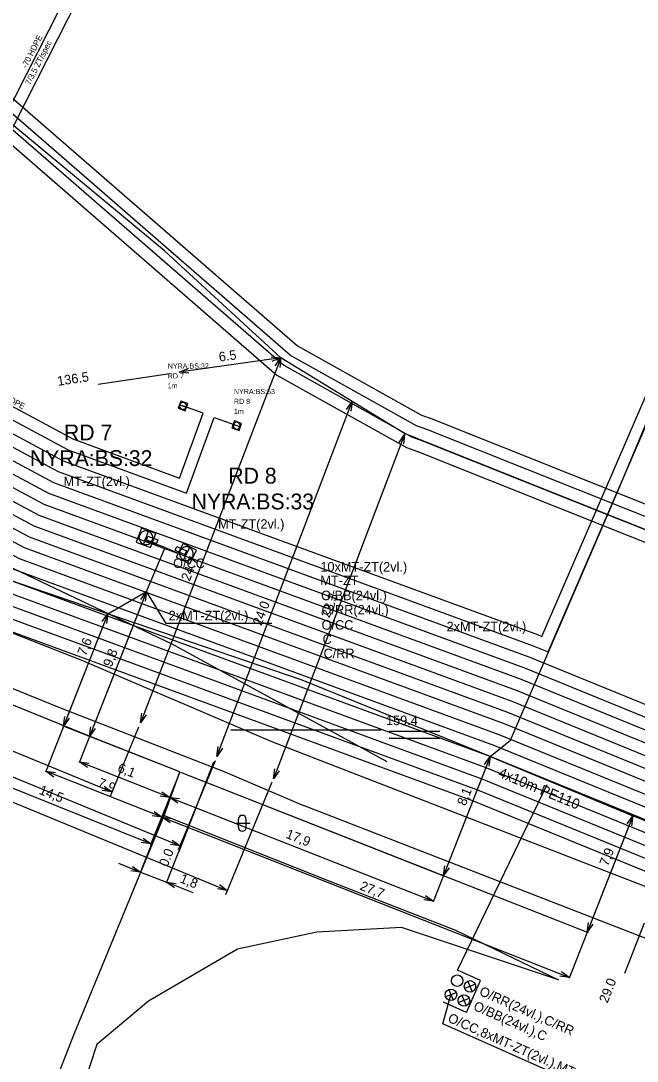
# Model space of a CAD drawing. Extents: x -836739 to -834468, y -1071001 to -1070126.
# Drawn here: x -836379.8 to -836340.8, y -1070425.8 to -1070360.1 of the extents above; entities that cross this region are included whole.
import ezdxf

# ---------------------------------------------------------------- set-up
doc = ezdxf.new("R2010")
doc.units = 0
for name, color, linetype in [('f001_pol_linie', 7, 'Continuous'), ('f001_pol_znacky', 7, 'Continuous'), ('f002_inz_linie_mimo_CETIN', 7, 'Continuous'), ('f003_opt_sit_texty', 7, 'Continuous'), ('f003_opt_sit_znacky', 7, 'Continuous'), ('f003_vynaseci_cary', 7, 'Continuous'), ('f006_osa_trasy', 7, 'Continuous'), ('f006_stp_koty', 7, 'Continuous'), ('f006_stp_linie', 7, 'Continuous'), ('f006_stp_texty', 7, 'Continuous'), ('f007_rezkynet_linie', 7, 'Continuous'), ('f007_rezkynet_texty', 7, 'Continuous'), ('f007_rezkynet_znacky', 7, 'Continuous'), ('f309_rozvadec_opt', 7, 'Continuous'), ('f309_rozvadec_opt_ann', 7, 'Continuous'), ('f309_trubicka', 7, 'Continuous'), ('f309_trubicka_ann', 7, 'Continuous'), ('f309_trubka', 7, 'Continuous')]:
    doc.layers.add(name, color=color, linetype=linetype)

msp = doc.modelspace()

# ---------------------------------------------------------------- linework, layer by layer
at = {"layer": 'f001_pol_linie'}
for points in [[(-836356.62, -1070406.87), (-836370.19, -1070399.44), (-836385.43, -1070392.2), (-836396.38, -1070386.03), (-836404.41, -1070381.11), (-836409.87, -1070376.61), (-836425.28, -1070363.93), (-836449.03, -1070345.44), (-836455, -1070340), (-836462.64, -1070329.11), (-836464.81, -1070325.47), (-836465.74, -1070321.03), (-836464.89, -1070314.87), (-836461.62, -1070306.74), (-836456.41, -1070297.54), (-836450.95, -1070288.2), (-836447.03, -1070272.79), (-836441.38, -1070260.76)], [(-836363.94, -1070405.58), (-836375.83, -1070400.5), (-836396.2, -1070392.51), (-836412.22, -1070385.35), (-836415.3, -1070382.95)], [(-836417.67, -1070386.5), (-836404.61, -1070392.58), (-836394.98, -1070396.26), (-836377.21, -1070403.49), (-836366.86, -1070407.51), (-836361.89, -1070409.63)], [(-836369.71, -1070407.51), (-836374.95, -1070405.45), (-836388.98, -1070399.76), (-836393.4, -1070397.9)], [(-836015.21, -1070459.49), (-836021.84, -1070470.53), (-836029.29, -1070480.55), (-836039.31, -1070497.89), (-836043.1, -1070509.87), (-836044.22, -1070522.08), (-836111.13, -1070487.77), (-836123.74, -1070483.53), (-836128.61, -1070481.99), (-836211.76, -1070460.38), (-836245.95, -1070449.75), (-836279.43, -1070438.33), (-836363.94, -1070405.58)], [(-836407.72, -1070434.26), (-836402.65, -1070436.98), (-836392.21, -1070442.72), (-836384.11, -1070447.06), (-836383.25, -1070443.91), (-836379.69, -1070432.5), (-836376.35, -1070424), (-836370.7, -1070410.27), (-836369.71, -1070407.51)], [(-836046.6, -1070544.35), (-836045.64, -1070538.23), (-836044.38, -1070528.39), (-836045.14, -1070525.37), (-836047.92, -1070523.71), (-836112.97, -1070490.6), (-836124.66, -1070486.54), (-836132.47, -1070484.33), (-836212.77, -1070463.28), (-836247.95, -1070452.55), (-836280.73, -1070441.12), (-836361.89, -1070409.63)], [(-836370.7, -1070410.27), (-836360.12, -1070414.44), (-836352.3, -1070417.49), (-836345.8, -1070420.64)], [(-836345.8, -1070420.64), (-836355.7, -1070417.34), (-836361.05, -1070417.62), (-836366.07, -1070418.7), (-836371.68, -1070421.97), (-836374.95, -1070424.71), (-836382.62, -1070447.97)]]:
    msp.add_lwpolyline(points, dxfattribs=at)
at = {"layer": 'f001_pol_znacky'}
for p, q in [((-836366.01, -1070411), (-836366.01, -1070410.5)), ((-836365.51, -1070411), (-836365.51, -1070410.5)), ((-836366.26, -1070410.75), (-836365.26, -1070410.75))]:
    msp.add_line(p, q, dxfattribs=at)
for centre, start, end in [((-836365.76, -1070410.5), 0, 179.99999), ((-836365.76, -1070411), 179.99999, 359.99999)]:
    msp.add_arc(centre, 0.25, start, end, dxfattribs=at)
at = {"layer": 'f002_inz_linie_mimo_CETIN'}
for points in [[(-836371.81, -1070392.85), (-836371.72, -1070392.62), (-836371.09, -1070392.85), (-836371.18, -1070393.08)], [(-836371.81, -1070392.85), (-836371.72, -1070392.62), (-836371.09, -1070392.85), (-836371.18, -1070393.08)], [(-836371.81, -1070392.85), (-836371.18, -1070393.08)], [(-836371.81, -1070392.85), (-836371.18, -1070393.08)], [(-836370, -1070393.52), (-836369.9, -1070393.29), (-836369.29, -1070393.55), (-836369.39, -1070393.78)], [(-836370, -1070393.52), (-836369.9, -1070393.29), (-836369.29, -1070393.55), (-836369.39, -1070393.78)], [(-836370, -1070393.52), (-836369.39, -1070393.78)], [(-836370, -1070393.52), (-836369.39, -1070393.78)]]:
    msp.add_lwpolyline(points, dxfattribs=at)
at = {"layer": 'f003_opt_sit_znacky'}
for p, q in [((-836371.698, -1070392.326), (-836372.002, -1070393.134)), ((-836371.699, -1070392.326), (-836371.698, -1070392.326)), ((-836369.097, -1070393.344), (-836369.483, -1070394.116)), ((-836369.097, -1070393.344), (-836369.097, -1070393.344))]:
    msp.add_line(p, q, dxfattribs=at)
for points in [[(-836372.466, -1070393.012), (-836371.567, -1070393.349), (-836371.23, -1070392.45), (-836372.129, -1070392.113)], [(-836369.932, -1070393.946), (-836369.073, -1070394.375), (-836368.644, -1070393.516), (-836369.502, -1070393.087)]]:
    msp.add_lwpolyline(points, close=True, dxfattribs=at)
for centre, start, end in [((-836371.847, -1070392.731), 69.80775, 249.08016), ((-836371.847, -1070392.731), 249.03941, 69.84764), ((-836369.288, -1070393.731), 63.79875, 243.07115), ((-836369.287, -1070393.732), 243.0304, 63.83864)]:
    msp.add_arc(centre, 0.432, start, end, dxfattribs=at)
at = {"layer": 'f003_vynaseci_cary'}
msp.add_lwpolyline([(-836363.89, -1070398.15), (-836370.57, -1070398.15), (-836371.81, -1070396.12)], dxfattribs=at)
at = {"layer": 'f006_osa_trasy'}
for points in [[(-836259.51, -1070422.49), (-836273.33, -1070418.13), (-836279.63, -1070415.33), (-836305.65, -1070405.26), (-836332.15, -1070395.46), (-836355.51, -1070386.15), (-836363.32, -1070381.37), (-836370.68, -1070374.62), (-836386.63, -1070361.4), (-836412.6, -1070344.19), (-836444.52, -1070318.16), (-836450.35, -1070293.64), (-836451.12, -1070284.95), (-836453.47, -1070277.02), (-836456.68, -1070270.62)], [(-836350.1, -1070406.54), (-836348.82, -1070405.5), (-836341.98, -1070389.64), (-836337.19, -1070378.21), (-836332.66, -1070368.05), (-836330.1, -1070369.07), (-836327.64, -1070363.27)], [(-836374.26, -1070397.52), (-836380.46, -1070395.41), (-836397.84, -1070386.09), (-836399.2, -1070385.59)], [(-836370.64, -1070393.35), (-836371.91, -1070392.88), (-836371.85, -1070392.73)], [(-836374.26, -1070397.52), (-836371.81, -1070396.12), (-836370.64, -1070393.35)], [(-836370.64, -1070393.35), (-836369.37, -1070393.89), (-836369.29, -1070393.73)], [(-836350.1, -1070406.54), (-836361.97, -1070401.72), (-836374.26, -1070397.52)], [(-836322.53, -1070417.81), (-836341.09, -1070410.29), (-836350.1, -1070406.54)]]:
    msp.add_lwpolyline(points, dxfattribs=at)
at = {"layer": 'f006_stp_koty'}
for p, q in [((-836371.832, -1070396.176), (-836376.061, -1070406.932)), ((-836371.81, -1070396.12), (-836375.407, -1070405.27)), ((-836374.26, -1070397.52), (-836377.053, -1070404.623)), ((-836374.282, -1070397.576), (-836378.194, -1070407.528)), ((-836369.766, -1070407.488), (-836377.108, -1070404.601)), ((-836369.766, -1070407.488), (-836375.463, -1070405.248)), ((-836371.531, -1070412.053), (-836384.999, -1070406.656)), ((-836350.122, -1070406.596), (-836353.709, -1070415.72)), ((-836350.1, -1070406.54), (-836353.055, -1070414.057)), ((-836370.342, -1070409.116), (-836376.039, -1070406.877)), ((-836370.83, -1070410.359), (-836378.173, -1070407.472)), ((-836369.732, -1070407.566), (-836372.216, -1070413.884)), ((-836369.732, -1070407.566), (-836371.553, -1070412.109)), ((-836369.732, -1070407.566), (-836370.852, -1070410.415)), ((-836369.732, -1070407.566), (-836370.852, -1070410.415)), ((-836369.732, -1070407.566), (-836370.363, -1070409.172)), ((-836369.732, -1070407.566), (-836370.363, -1070409.172)), ((-836369.654, -1070407.532), (-836352.999, -1070414.079)), ((-836369.654, -1070407.532), (-836343.919, -1070417.649)), ((-836368.086, -1070408.213), (-836370.57, -1070414.531)), ((-836370.342, -1070409.116), (-836353.687, -1070415.664)), ((-836370.83, -1070410.359), (-836345.095, -1070420.476)), ((-836341.112, -1070410.346), (-836345.116, -1070420.532)), ((-836341.09, -1070410.29), (-836343.975, -1070417.627)), ((-836373.59, -1070413.279), (-836372.194, -1070413.828)), ((-836372.194, -1070413.828), (-836370.548, -1070414.475)), ((-836368.861, -1070415.138), (-836370.548, -1070414.475))]:
    msp.add_line(p, q, dxfattribs=at)
for points in [[(-836363.32, -1070381.37), (-836372.191, -1070404.406)], [(-836363.32, -1070381.37), (-836369.749, -1070382.285)], [(-836363.935, -1070381.306), (-836363.32, -1070381.37), (-836363.892, -1070381.603)], [(-836363.675, -1070381.876), (-836363.32, -1070381.37), (-836363.395, -1070381.983)], [(-836370.331, -1070382.379), (-836374.864, -1070383.063)], [(-836369.133, -1070382.348), (-836369.749, -1070382.285), (-836369.176, -1070382.051)], [(-836435.495, -1070383.458), (-836373.991, -1070408.776)], [(-836367.368, -1070406.528), (-836358.831, -1070384.117)], [(-836359.184, -1070384.624), (-836358.831, -1070384.117), (-836358.904, -1070384.731)], [(-836436.07, -1070384.855), (-836369.694, -1070412.179)], [(-836436.625, -1070386.205), (-836366.711, -1070414.986)], [(-836355.51, -1070386.2), (-836363.79, -1070407.938)], [(-836355.863, -1070386.707), (-836355.51, -1070386.2), (-836355.583, -1070386.814)], [(-836372.169, -1070396.624), (-836371.81, -1070396.12), (-836371.89, -1070396.733)], [(-836374.619, -1070398.024), (-836374.26, -1070397.52), (-836374.34, -1070398.133)], [(-836376.693, -1070404.12), (-836377.053, -1070404.623), (-836376.973, -1070404.01)], [(-836371.835, -1070403.899), (-836372.191, -1070404.406), (-836372.115, -1070403.792)], [(-836375.048, -1070404.767), (-836375.407, -1070405.27), (-836375.327, -1070404.657)], [(-836372.306, -1070404.683), (-836374.105, -1070409.054)], [(-836366.48, -1070404.853), (-836356.983, -1070404.853)], [(-836356.49, -1070404.94), (-836353.28, -1070404.94)], [(-836356.49, -1070405.38), (-836353.28, -1070405.38)], [(-836367.014, -1070406.02), (-836367.368, -1070406.528), (-836367.294, -1070405.913)], [(-836350.459, -1070407.044), (-836350.1, -1070406.54), (-836350.18, -1070407.153)], [(-836375.535, -1070407.236), (-836376.039, -1070406.877), (-836375.425, -1070406.957)], [(-836367.482, -1070406.805), (-836369.808, -1070412.456)], [(-836367.572, -1070406.894), (-836369.775, -1070412.548)], [(-836363.436, -1070407.43), (-836363.79, -1070407.938), (-836363.716, -1070407.323)], [(-836377.669, -1070407.831), (-836378.173, -1070407.472), (-836377.559, -1070407.552)], [(-836374.488, -1070408.408), (-836373.991, -1070408.776), (-836374.602, -1070408.686)], [(-836363.904, -1070408.166), (-836366.825, -1070415.263)], [(-836370.845, -1070408.757), (-836370.342, -1070409.116), (-836370.955, -1070409.036)], [(-836369.838, -1070409.476), (-836370.342, -1070409.116), (-836369.728, -1070409.196)], [(-836371.333, -1070410), (-836370.83, -1070410.359), (-836371.443, -1070410.279)], [(-836370.326, -1070410.718), (-836370.83, -1070410.359), (-836370.217, -1070410.439)], [(-836341.449, -1070410.794), (-836341.09, -1070410.29), (-836341.17, -1070410.903)], [(-836372.032, -1070411.691), (-836371.531, -1070412.053), (-836372.143, -1070411.969)], [(-836370.191, -1070411.811), (-836369.694, -1070412.179), (-836370.305, -1070412.089)], [(-836372.697, -1070413.469), (-836372.194, -1070413.828), (-836372.807, -1070413.748)], [(-836352.696, -1070413.554), (-836353.055, -1070414.057), (-836352.975, -1070413.444)], [(-836370.045, -1070414.834), (-836370.548, -1070414.475), (-836369.935, -1070414.555)], [(-836367.208, -1070414.618), (-836366.711, -1070414.986), (-836367.322, -1070414.896)], [(-836354.19, -1070415.305), (-836353.687, -1070415.664), (-836354.3, -1070415.584)], [(-836343.615, -1070417.124), (-836343.975, -1070417.627), (-836343.895, -1070417.014)], [(-836340.379, -1070417.053), (-836341.625, -1070420.232)], [(-836345.598, -1070420.117), (-836345.095, -1070420.476), (-836345.708, -1070420.396)]]:
    msp.add_lwpolyline(points, dxfattribs=at)
at = {"layer": 'f006_stp_linie'}
msp.add_lwpolyline([(-836350.1, -1070406.54), (-836341.09, -1070410.29)], dxfattribs=at)
at = {"layer": 'f007_rezkynet_linie'}
for points in [[(-836352.169, -1070420.019), (-836346.503, -1070408.308)], [(-836341.211, -1070428.682), (-836353.103, -1070423.416), (-836352.583, -1070421.575)]]:
    msp.add_lwpolyline(points, dxfattribs=at)
at = {"layer": 'f007_rezkynet_znacky'}
for p, q in [((-836350.706, -1070420.667), (-836352.169, -1070420.019)), ((-836351.038, -1070420.917), (-836351.716, -1070421.178)), ((-836351.599, -1070422.685), (-836350.706, -1070420.667)), ((-836351.508, -1070420.709), (-836351.246, -1070421.386)), ((-836352.244, -1070421.444), (-836352.922, -1070421.705)), ((-836352.714, -1070421.236), (-836352.452, -1070421.913)), ((-836351.422, -1070421.808), (-836352.099, -1070422.069)), ((-836351.892, -1070421.6), (-836351.629, -1070422.277)), ((-836353.077, -1070422.031), (-836351.614, -1070422.678))]:
    msp.add_line(p, q, dxfattribs=at)
for centre in [(-836352.191, -1070420.687), (-836351.377, -1070421.048), (-836352.583, -1070421.575), (-836351.761, -1070421.939)]:
    msp.add_circle(centre, 0.363, dxfattribs=at)
at = {"layer": 'f309_rozvadec_opt'}
for p, q in [((-836369.711, -1070384.332), (-836369.306, -1070384.481)), ((-836369.711, -1070384.332), (-836369.711, -1070384.332)), ((-836365.907, -1070385.724), (-836366.312, -1070385.575)), ((-836365.907, -1070385.724), (-836365.907, -1070385.724))]:
    msp.add_line(p, q, dxfattribs=at)
for points in [[(-836369.365, -1070384.713), (-836369.2, -1070384.263), (-836369.651, -1070384.097), (-836369.816, -1070384.548)], [(-836366.253, -1070385.343), (-836366.418, -1070385.793), (-836365.967, -1070385.959), (-836365.802, -1070385.508)]]:
    msp.add_lwpolyline(points, close=True, dxfattribs=at)
for centre, start, end in [((-836369.508, -1070384.405), 160.21824, 339.49064), ((-836369.508, -1070384.405), 339.44989, 160.25813), ((-836366.11, -1070385.651), 159.46033, 340.26857), ((-836366.11, -1070385.651), 340.22868, 159.50108)]:
    msp.add_arc(centre, 0.216, start, end, dxfattribs=at)
at = {"layer": 'f309_trubicka'}
for points in [[(-836400.273, -1070369.489), (-836389.056, -1070373.818), (-836390.12, -1070377.18), (-836390.197, -1070377.426), (-836387.286, -1070378.986), (-836373.656, -1070352.184), (-836377.341, -1070350.282), (-836374.754, -1070345.274), (-836376.759, -1070344.239), (-836376.341, -1070343.429)], [(-836400.273, -1070369.489), (-836389.771, -1070373.592), (-836390.835, -1070376.954), (-836391.1, -1070377.793), (-836386.965, -1070380.009), (-836372.65, -1070351.86), (-836376.33, -1070349.96), (-836374.088, -1070345.618), (-836371.351, -1070347.031), (-836370.932, -1070346.22)], [(-836400.273, -1070369.489), (-836391.917, -1070372.915), (-836392.98, -1070376.276), (-836393.807, -1070378.894), (-836377.072, -1070387.864), (-836347.119, -1070398.841), (-836346.84, -1070398.955), (-836333.059, -1070367.084), (-836330.504, -1070368.102), (-836328.325, -1070362.967), (-836330.838, -1070361.855), (-836330.397, -1070360.859)], [(-836400.273, -1070369.489), (-836392.632, -1070372.689), (-836393.695, -1070376.05), (-836394.709, -1070379.261), (-836377.38, -1070388.55), (-836347.39, -1070399.54), (-836346.443, -1070399.927), (-836332.66, -1070368.05), (-836330.1, -1070369.07), (-836327.64, -1070363.27), (-836325.462, -1070364.234), (-836325.022, -1070363.239)], [(-836400.273, -1070369.489), (-836398.353, -1070370.882), (-836399.415, -1070374.242), (-836401.469, -1070380.743), (-836403.793, -1070387.056), (-836399.084, -1070388.826), (-836381.692, -1070398.154), (-836351.184, -1070409.34), (-836324.48, -1070420.23), (-836327.076, -1070426.64), (-836328.57, -1070426.6)], [(-836400.273, -1070369.489), (-836397.638, -1070371.108), (-836398.7, -1070374.468), (-836400.759, -1070380.986), (-836402.832, -1070386.616), (-836398.773, -1070388.142), (-836381.384, -1070397.468), (-836350.913, -1070408.64), (-836323.504, -1070419.818), (-836326.34, -1070426.82), (-836326.51, -1070428.61)], [(-836400.273, -1070369.489), (-836399.069, -1070370.656), (-836400.13, -1070374.016), (-836402.617, -1070381.89), (-836396.907, -1070384.038), (-836379.536, -1070393.352), (-836349.287, -1070404.44), (-836286.052, -1070430.233), (-836290.016, -1070440.999), (-836290.881, -1070443.349)], [(-836400.273, -1070369.489), (-836396.208, -1070371.559), (-836397.27, -1070374.92), (-836399.339, -1070381.472), (-836399.355, -1070381.515), (-836396.285, -1070382.67), (-836378.92, -1070391.98), (-836348.745, -1070403.04), (-836289.137, -1070427.354), (-836286.713, -1070421.411), (-836283.062, -1070422.901)], [(-836400.273, -1070369.489), (-836394.777, -1070372.011), (-836395.84, -1070375.372), (-836397.495, -1070380.612), (-836395.663, -1070381.302), (-836378.304, -1070390.608), (-836348.203, -1070401.64), (-836289.959, -1070425.398), (-836287.821, -1070420.156), (-836276.772, -1070391.607), (-836279.008, -1070390.66), (-836276.322, -1070384.183), (-836278.31, -1070383.359), (-836277.858, -1070382.269)], [(-836400.273, -1070369.489), (-836395.493, -1070371.785), (-836396.555, -1070375.146), (-836398.424, -1070381.064), (-836395.974, -1070381.986), (-836378.612, -1070391.294), (-836348.474, -1070402.34), (-836289.548, -1070426.376), (-836287.124, -1070420.433), (-836275.81, -1070391.2), (-836278.03, -1070390.26), (-836275.63, -1070384.47), (-836273.812, -1070385.224), (-836273.367, -1070384.131)], [(-836400.273, -1070369.489), (-836394.062, -1070372.237), (-836395.125, -1070375.598), (-836396.566, -1070380.161), (-836395.352, -1070380.618), (-836377.996, -1070389.922), (-836347.932, -1070400.94), (-836316.686, -1070413.686), (-836314.602, -1070408.659), (-836312.289, -1070409.618)], [(-836400.273, -1070369.489), (-836393.347, -1070372.463), (-836394.41, -1070375.824), (-836395.637, -1070379.709), (-836395.041, -1070379.934), (-836377.688, -1070389.236), (-836347.661, -1070400.24), (-836317.093, -1070412.71), (-836315.295, -1070408.372), (-836317.789, -1070407.338)], [(-836400.273, -1070369.489), (-836391.202, -1070373.141), (-836392.265, -1070376.502), (-836392.904, -1070378.527), (-836376.764, -1070387.178), (-836369.286, -1070389.919), (-836367.531, -1070385.13), (-836366.11, -1070385.651)], [(-836400.273, -1070369.489), (-836390.486, -1070373.366), (-836391.55, -1070376.728), (-836392.002, -1070378.16), (-836376.456, -1070386.492), (-836369.732, -1070388.957), (-836368.235, -1070384.872), (-836369.508, -1070384.405)], [(-836397.141, -1070372.024), (-836397.985, -1070374.694), (-836400.049, -1070381.229), (-836400.305, -1070381.924), (-836400.312, -1070381.956), (-836396.596, -1070383.354), (-836379.228, -1070392.666), (-836349.016, -1070403.74), (-836288.726, -1070428.332), (-836286.302, -1070422.389), (-836283.345, -1070423.595)]]:
    msp.add_lwpolyline(points, dxfattribs=at)
at = {"layer": 'f309_trubka'}
for points in [[(-836261.299, -1070421.137), (-836273.064, -1070417.427), (-836279.342, -1070414.637), (-836305.385, -1070404.559), (-836331.881, -1070394.76), (-836354.106, -1070385.902), (-836354.759, -1070385.663), (-836362.708, -1070381.226), (-836386.046, -1070360.976), (-836412.515, -1070343.515), (-836444.58, -1070317.908), (-836450.178, -1070294.362), (-836450.35, -1070293.64), (-836451.12, -1070284.95), (-836453.47, -1070277.02), (-836455.659, -1070272.655)], [(-836454.989, -1070272.319), (-836452.77, -1070276.743), (-836450.38, -1070284.809), (-836449.608, -1070293.52), (-836449.436, -1070294.242), (-836443.91, -1070317.483), (-836412.074, -1070342.908), (-836385.592, -1070360.377), (-836362.275, -1070380.609), (-836354.445, -1070384.979), (-836353.838, -1070385.201), (-836331.612, -1070394.06), (-836305.12, -1070403.858), (-836279.054, -1070413.944), (-836272.798, -1070416.724), (-836261.073, -1070420.421)], [(-836457, -1070273.327), (-836454.87, -1070277.574), (-836452.6, -1070285.232), (-836451.834, -1070293.88), (-836451.663, -1070294.602), (-836445.92, -1070318.758), (-836413.397, -1070344.729), (-836386.954, -1070362.174), (-836363.574, -1070382.46), (-836355.387, -1070387.031), (-836354.642, -1070387.304), (-836332.419, -1070396.16), (-836305.915, -1070405.961), (-836279.918, -1070416.023), (-836273.596, -1070418.833), (-836262.401, -1070422.363)], [(-836456.329, -1070272.991), (-836454.17, -1070277.297), (-836451.86, -1070285.091), (-836451.092, -1070293.76), (-836445.25, -1070318.333), (-836412.956, -1070344.122), (-836386.5, -1070361.575), (-836363.141, -1070381.843), (-836355.073, -1070386.347), (-836354.374, -1070386.603), (-836332.15, -1070395.46), (-836305.65, -1070405.26), (-836279.63, -1070415.33), (-836273.33, -1070418.13), (-836262.175, -1070421.648)], [(-836257.543, -1070422.322), (-836258.258, -1070422.096), (-836259.283, -1070421.772), (-836260.99, -1070422.47), (-836266.6, -1070439.21), (-836271.52, -1070438.59), (-836350.1, -1070406.54), (-836380.46, -1070395.41), (-836397.84, -1070386.09), (-836408, -1070382.27), (-836428.93, -1070370.15), (-836446.35, -1070358.45), (-836497.8, -1070313.84), (-836500.259, -1070310.812)], [(-836499.139, -1070311.001), (-836497.259, -1070313.316), (-836445.894, -1070357.853), (-836428.533, -1070369.513), (-836407.678, -1070381.59), (-836397.529, -1070385.406), (-836380.152, -1070394.724), (-836349.829, -1070405.84), (-836271.328, -1070437.858), (-836267.116, -1070438.389), (-836261.592, -1070421.906), (-836259.316, -1070420.975), (-836258.032, -1070421.38), (-836257.317, -1070421.606)], [(-836501.069, -1070312.194), (-836498.882, -1070314.888), (-836447.262, -1070359.644), (-836429.724, -1070371.424), (-836408.644, -1070383.63), (-836398.462, -1070387.458), (-836381.076, -1070396.782), (-836350.642, -1070407.94), (-836271.904, -1070440.054), (-836265.568, -1070440.852), (-836259.786, -1070423.598), (-836259.218, -1070423.366), (-836257.995, -1070423.753)], [(-836499.902, -1070312.441), (-836498.341, -1070314.364), (-836446.806, -1070359.047), (-836429.327, -1070370.787), (-836408.322, -1070382.95), (-836398.151, -1070386.774), (-836380.768, -1070396.096), (-836350.371, -1070407.24), (-836271.712, -1070439.322), (-836266.084, -1070440.031), (-836260.388, -1070423.034), (-836259.25, -1070422.569), (-836257.769, -1070423.038)], [(-836400.845, -1070373.79), (-836403.452, -1070382.042), (-836403.525, -1070382.35), (-836397.218, -1070384.722), (-836379.844, -1070394.038), (-836349.558, -1070405.14), (-836287.006, -1070430.654), (-836290.72, -1070440.74)]]:
    msp.add_lwpolyline(points, dxfattribs=at)

# ---------------------------------------------------------------- texts
at = {"layer": 'f003_opt_sit_texty'}
for s, height, p in [('RD 7', 1, (-836377.02, -1070386.58)), ('NYRA:BS:32', 1, (-836379.17, -1070388.2)), ('RD 8', 1, (-836366.64, -1070389.31)), ('MT-ZT(2vl.)', 0.6, (-836377.05, -1070389.47)), ('NYRA:BS:33', 1, (-836368.96, -1070390.94)), ('MT-ZT(2vl.)', 0.6, (-836367.29, -1070392.16)), ('O/CC', 0.6, (-836370.13, -1070394.64)), ('10xMT-ZT(2vl.)', 0.6, (-836360.83, -1070394.86)), ('MT-ZT', 0.6, (-836360.83, -1070395.72)), ('O/BB(24vl.)', 0.6, (-836360.78, -1070396.67)), ('2xMT-ZT(2vl.)', 0.6, (-836370.41, -1070397.94)), ('O/RR(24vl.)', 0.6, (-836360.75, -1070397.57)), ('O/CC', 0.6, (-836360.75, -1070398.53)), ('2xMT-ZT(2vl.)', 0.6, (-836352.86, -1070398.63)), ('C', 0.6, (-836360.69, -1070399.43)), ('C/RR', 0.6, (-836360.63, -1070400.33))]:
    msp.add_text(s, height=height, dxfattribs=at).set_placement(p)
at = {"layer": 'f006_stp_koty'}
for s, rotation, p in [('6.5', 8.11, (-836367.201, -1070381.618)), ('136.5', 8.58, (-836377.399, -1070383.142)), ('24.7', 68.94, (-836369.086, -1070395.51)), ('24.0', 69.15, (-836364.565, -1070398.328)), ('23.3', 69.15, (-836360.259, -1070397.826)), ('7,6', 68.53873, (-836375.645, -1070400.223)), ('9,8', 68.53873, (-836374.022, -1070400.927)), ('6,1', 338.53873, (-836373.69, -1070407.478)), ('7,9', 338.53873, (-836374.946, -1070408.418)), ('14,5', 338.16266, (-836378.647, -1070408.878)), ('8,1', 68.53873, (-836351.661, -1070409.692)), ('17,9', 338.53873, (-836363.059, -1070411.657)), ('0.0', 68.71, (-836370.481, -1070413.539)), ('7,9', 68.53873, (-836342.672, -1070413.495)), ('1,8', 338.53873, (-836369.75, -1070414.467)), ('27,7', 338.53873, (-836358.383, -1070414.93)), ('29.0', 68.59, (-836342.695, -1070422.138))]:
    msp.add_text(s, height=0.6, rotation=rotation, dxfattribs=at).set_placement(p)
msp.add_text('159.4', height=0.6, dxfattribs=at).set_placement((-836356.683, -1070404.553))
at = {"layer": 'f006_stp_texty'}
msp.add_text('4x10m PE110', height=0.65, rotation=337.40272, dxfattribs=at).set_placement((-836349.65, -1070407.8))
at = {"layer": 'f007_rezkynet_texty'}
for s, p in [('O/RR(24vl.),C/RR', (-836350.842, -1070421.571)), ('O/BB(24vl.),C', (-836351.215, -1070422.507)), ('O/CC,8xMT-ZT(2vl.),MT-ZT', (-836352.83, -1070423.257))]:
    msp.add_text(s, height=0.6, rotation=336.11529, dxfattribs=at).set_placement(p)
at = {"layer": 'f309_rozvadec_opt_ann'}
for s, p in [('NYRA:BS:32', (-836370.47, -1070382.048)), ('RD 7', (-836370.47, -1070382.673)), ('1m', (-836370.47, -1070383.298)), ('NYRA:BS:53', (-836366.29, -1070383.658)), ('RD 8', (-836366.29, -1070384.283)), ('1m', (-836366.29, -1070384.908))]:
    msp.add_text(s, height=0.325, dxfattribs=at).set_placement(p)
at = {"layer": 'f309_trubicka_ann'}
for s, rotation, p in [('-70 HDPE', 63.04465, (-836379.388, -1070363.125)), ('7/3,5 ZT/spec', 63.04465, (-836379.167, -1070364.18)), ('-53 HDPE', 331.81057, (-836381.596, -1070383.567))]:
    msp.add_text(s, height=0.375, rotation=rotation, dxfattribs=at).set_placement(p)

doc.saveas('drawing.dxf')
